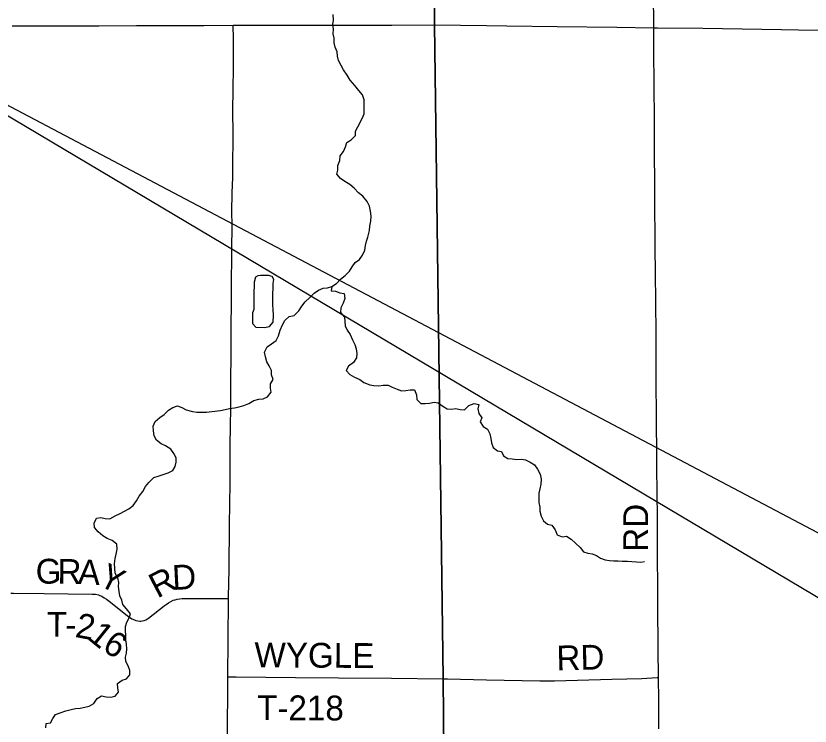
# Model space of a CAD drawing. Extents: x 0 to 34, y 0 to 22.
# Drawn here: x 26.924 to 28.741, y 13.678 to 15.303 of the extents above; entities that cross this region are included whole.
import ezdxf

# ---------------------------------------------------------------- set-up
doc = ezdxf.new("R2010")
doc.units = 0
for name, color, linetype in [('GM_X_Corporation', 7, 'Continuous'), ('GM_X_County_Road', 7, 'Continuous'), ('GM_X_County_Road_Text', 7, 'Continuous'), ('GM_X_Minor_Lake', 7, 'Continuous'), ('GM_X_Minor_River', 7, 'Continuous'), ('GM_X_State_Route', 7, 'Continuous'), ('GM_X_Township_Road', 7, 'Continuous'), ('GM_X_Township_Road_Text', 7, 'Continuous'), ('SH_Text', 7, 'Continuous')]:
    doc.layers.add(name, color=color, linetype=linetype)

msp = doc.modelspace()

# ---------------------------------------------------------------- linework, layer by layer
at = {"layer": 'GM_X_Corporation'}
for points in [[(26.7975, 12.7429), (27.3609, 12.7486), (27.363, 12.7493), (27.3691, 12.7502), (27.3721, 12.7505), (27.377, 12.7508), (27.3825, 12.7513), (27.879, 12.748), (27.9112, 12.7478), (27.9109, 12.7769), (27.9019, 13.7865), (27.8823, 15.2828), (27.8801, 15.6288), (27.88, 15.6409), (27.8849, 16.5038), (27.8821, 16.7067), (23.0715, 16.7067)], [(29.8715, 12.7899), (29.8715, 16.7067), (27.8821, 16.7067), (27.8849, 16.5038), (27.88, 15.6409), (27.8801, 15.6288), (27.8823, 15.2828), (27.9019, 13.7865), (27.9109, 12.7769)]]:
    msp.add_lwpolyline(points, dxfattribs=at)
at = {"layer": 'GM_X_County_Road'}
for points in [[(28.3839, 15.2757), (28.3837, 15.2989), (28.3832, 15.3343), (28.383, 15.3648), (28.3826, 15.3927), (28.3824, 15.4256), (28.3823, 15.4437), (28.3822, 15.4716), (28.3819, 15.4952), (28.3816, 15.522), (28.3814, 15.5425), (28.3812, 15.5598), (28.3809, 15.5896), (28.3807, 15.6017)], [(28.3948, 13.7889), (28.3944, 13.8084), (28.3939, 13.8336), (28.3936, 13.8749), (28.3932, 13.9339), (28.3927, 13.9799), (28.3927, 14.0178), (28.3926, 14.0433), (28.3926, 14.0713), (28.3924, 14.0887), (28.3923, 14.1266), (28.3923, 14.1519), (28.392, 14.1736), (28.3919, 14.1929), (28.3917, 14.2084), (28.3915, 14.2183), (28.3913, 14.227), (28.391, 14.2543), (28.3908, 14.2742), (28.3906, 14.2972), (28.3905, 14.3257), (28.3902, 14.3493), (28.3899, 14.3705), (28.3899, 14.3935), (28.3897, 14.4158), (28.3895, 14.4376), (28.3896, 14.4637), (28.3894, 14.4991), (28.3894, 14.5203), (28.3894, 14.5302), (28.389, 14.5687), (28.3889, 14.5942), (28.3888, 14.6296), (28.3883, 14.6688), (28.388, 14.6937), (28.3876, 14.7334), (28.3873, 14.7539), (28.3871, 14.7657), (28.387, 14.7869), (28.387, 14.8111), (28.3865, 14.8521), (28.3863, 14.8714), (28.3862, 14.8975), (28.386, 14.9366), (28.3857, 14.9727), (28.3856, 15.0006), (28.3856, 15.0404), (28.3854, 15.0647), (28.3853, 15.0914), (28.3848, 15.1175), (28.3845, 15.1535), (28.3844, 15.1715), (28.3841, 15.1964), (28.3838, 15.2318), (28.3839, 15.2573), (28.3839, 15.2757)], [(28.3957, 13.6713), (28.3952, 13.7432), (28.3949, 13.783), (28.3948, 13.7889)]]:
    msp.add_lwpolyline(points, dxfattribs=at)
at = {"layer": 'GM_X_Minor_Lake'}
msp.add_line((27.469, 14.6738), (27.4691, 14.6313), dxfattribs=at)
msp.add_lwpolyline([(27.4691, 14.6313), (27.4661, 14.6233), (27.4659, 14.6119), (27.4656, 14.5986), (27.4737, 14.5907), (27.4934, 14.5898), (27.5043, 14.5922), (27.5133, 14.6022), (27.5135, 14.6177), (27.513, 14.631), (27.5121, 14.6417), (27.512, 14.6553), (27.5122, 14.6667), (27.5128, 14.6796), (27.5131, 14.6903), (27.5149, 14.6998), (27.511, 14.7062), (27.5027, 14.7091), (27.4837, 14.7089), (27.4777, 14.7077), (27.4728, 14.705), (27.4699, 14.6936), (27.4696, 14.6818), (27.469, 14.6738)], dxfattribs=at)
at = {"layer": 'GM_X_Minor_River'}
for points in [[(27.7064, 15.0488), (27.7168, 15.0679), (27.7213, 15.0789), (27.7215, 15.0892), (27.721, 15.1006), (27.7213, 15.1105), (27.7177, 15.1222), (27.7093, 15.132), (27.6997, 15.1436), (27.6893, 15.1557), (27.682, 15.167), (27.6739, 15.1798), (27.6689, 15.1896), (27.6623, 15.2005), (27.6603, 15.2104), (27.6598, 15.2206), (27.6552, 15.2312), (27.6528, 15.2411), (27.6527, 15.2517), (27.6503, 15.2619), (27.6513, 15.2722), (27.6493, 15.2835), (27.6507, 15.2934), (27.6502, 15.3063)], [(27.2834, 14.2622), (27.289, 14.2718), (27.2911, 14.2817), (27.291, 14.2912), (27.2856, 14.3018), (27.2787, 14.3116), (27.2665, 14.319), (27.257, 14.3235), (27.2463, 14.3321), (27.2405, 14.3419), (27.2392, 14.3532), (27.2383, 14.3643), (27.2431, 14.3746), (27.2536, 14.3842), (27.2634, 14.3907), (27.2735, 14.4007), (27.2833, 14.4066), (27.2939, 14.4105), (27.3041, 14.4068), (27.314, 14.4012), (27.3281, 14.3972), (27.3383, 14.3958), (27.349, 14.3959), (27.3603, 14.3964), (27.3728, 14.3977), (27.3925, 14.4002), (27.403, 14.4023), (27.4132, 14.4043), (27.4242, 14.4056), (27.4356, 14.408), (27.4457, 14.4115), (27.4574, 14.4162), (27.4691, 14.4224), (27.48, 14.426), (27.4899, 14.4268), (27.4997, 14.4311), (27.5083, 14.4415), (27.507, 14.451), (27.5073, 14.4605), (27.5133, 14.4708), (27.509, 14.4817), (27.5089, 14.4912), (27.5042, 14.5018), (27.4984, 14.5116), (27.4956, 14.523), (27.4932, 14.5336), (27.4995, 14.5454), (27.5093, 14.5524), (27.5198, 14.5597), (27.5254, 14.5704), (27.5287, 14.5837), (27.5346, 14.5956), (27.5394, 14.6059), (27.5495, 14.6151), (27.5612, 14.6176), (27.5717, 14.6279), (27.5784, 14.6386), (27.5859, 14.6482), (27.5971, 14.6582), (27.6069, 14.6682), (27.6167, 14.6752), (27.6272, 14.6795), (27.6374, 14.6807), (27.6476, 14.6835), (27.6582, 14.6905), (27.6668, 14.7004), (27.678, 14.7089), (27.6878, 14.7185), (27.6937, 14.7289), (27.7004, 14.7384), (27.7102, 14.7454), (27.7177, 14.755), (27.7225, 14.7664), (27.7242, 14.7771), (27.7268, 14.7874), (27.7297, 14.7969), (27.7333, 14.8117), (27.734, 14.8216), (27.7361, 14.833), (27.7375, 14.8448), (27.7358, 14.8562), (27.7331, 14.8672), (27.728, 14.8781), (27.7184, 14.8902), (27.7085, 14.898), (27.6981, 14.9085), (27.6882, 14.9172), (27.6768, 14.9239), (27.6668, 14.9306), (27.6584, 14.9407), (27.6606, 14.9502), (27.6608, 14.9609), (27.6652, 14.9723), (27.6666, 14.9826), (27.6741, 14.9929), (27.6785, 15.0029), (27.6815, 15.0135), (27.6912, 15.0193), (27.7014, 15.029), (27.7016, 15.0388), (27.7064, 15.0488)], [(27.6476, 14.6835), (27.6458, 14.674), (27.6553, 14.673), (27.6652, 14.6693), (27.6754, 14.6679), (27.6767, 14.6561), (27.673, 14.6455), (27.6675, 14.6348), (27.6672, 14.6241), (27.676, 14.6136), (27.6773, 14.6034), (27.6774, 14.5939), (27.6824, 14.584), (27.689, 14.5739), (27.6948, 14.5614), (27.6998, 14.5512), (27.703, 14.541), (27.7042, 14.53), (27.7036, 14.5205), (27.6965, 14.5098), (27.6856, 14.5013), (27.6801, 14.4917), (27.6881, 14.482), (27.6992, 14.4764), (27.711, 14.4705), (27.7205, 14.4641), (27.7342, 14.4586), (27.7437, 14.4568), (27.7551, 14.4565), (27.7649, 14.4582), (27.7759, 14.4576), (27.7854, 14.4531), (27.7964, 14.4483), (27.8067, 14.4446), (27.8169, 14.4459), (27.8267, 14.4471), (27.8366, 14.4473), (27.8413, 14.4355), (27.8414, 14.4249), (27.851, 14.4159), (27.8608, 14.416), (27.871, 14.4165), (27.8812, 14.4189), (27.8907, 14.4171), (27.9014, 14.4097), (27.9109, 14.4037), (27.9208, 14.4027), (27.9306, 14.4043), (27.9409, 14.4022), (27.9507, 14.4011), (27.9605, 14.4111), (27.9725, 14.4162), (27.9839, 14.4133), (27.981, 14.4038), (27.9834, 14.3932), (27.9907, 14.3834), (27.9863, 14.3738), (27.9936, 14.3633), (28.0031, 14.3573), (28.0089, 14.3468), (28.0109, 14.3358), (28.0129, 14.3256), (28.0165, 14.3153), (28.026, 14.3079), (28.0355, 14.3061), (28.0402, 14.2959), (28.0497, 14.2899), (28.0599, 14.2889), (28.0705, 14.2875), (28.0808, 14.2888), (28.0906, 14.287), (28.1013, 14.2818), (28.1108, 14.2758), (28.1174, 14.2653), (28.1239, 14.2543), (28.126, 14.243), (28.1253, 14.2316), (28.1232, 14.2205), (28.121, 14.211), (28.1208, 14.1992), (28.1209, 14.1894), (28.1229, 14.1788), (28.123, 14.1693), (28.1258, 14.1579), (28.1312, 14.1477), (28.1407, 14.1399), (28.1502, 14.1373), (28.1583, 14.1264), (28.163, 14.1154), (28.1744, 14.111), (28.1842, 14.1119), (28.1945, 14.1056), (28.2049, 14.0966), (28.2156, 14.0864), (28.2229, 14.0763), (28.2331, 14.0737), (28.243, 14.072), (28.2525, 14.0683), (28.262, 14.0619), (28.2723, 14.0583), (28.2826, 14.0565)], [(26.993, 13.6737), (26.994, 13.6835), (27.0039, 13.6852), (27.0091, 13.6947), (27.0154, 13.7043), (27.026, 13.7082), (27.0384, 13.7122), (27.0509, 13.7154), (27.0611, 13.7177), (27.0713, 13.7186), (27.0822, 13.721), (27.0921, 13.7231), (27.1026, 13.7296), (27.1104, 13.7407), (27.1202, 13.7465), (27.1312, 13.7448), (27.1411, 13.7438), (27.1513, 13.7458), (27.1595, 13.7554), (27.1579, 13.7652), (27.1566, 13.7751), (27.1675, 13.7828), (27.1777, 13.7856), (27.1848, 13.7951), (27.1851, 13.805), (27.1812, 13.8152), (27.1761, 13.8258), (27.1749, 13.8353), (27.1774, 13.8448), (27.1785, 13.8547), (27.1772, 13.8653), (27.176, 13.8752), (27.1759, 13.8854), (27.1754, 13.8953), (27.1753, 13.9055), (27.1782, 13.9154), (27.1834, 13.925), (27.1863, 13.9349), (27.1775, 13.9462), (27.1694, 13.956), (27.1666, 13.9658), (27.1624, 13.976), (27.1607, 13.9859), (27.1595, 13.9969), (27.1597, 14.0064), (27.1574, 14.017), (27.1519, 14.0279), (27.151, 14.0389), (27.1498, 14.0492), (27.1516, 14.061), (27.1541, 14.0712), (27.1559, 14.0823), (27.1557, 14.0937), (27.1447, 14.1026), (27.1336, 14.1067), (27.123, 14.1134), (27.113, 14.122), (27.1042, 14.1318), (27.1033, 14.1417), (27.1085, 14.1531), (27.1187, 14.1547), (27.1286, 14.1526), (27.1392, 14.1519), (27.1516, 14.1589), (27.1629, 14.164), (27.1727, 14.1698), (27.1829, 14.1745), (27.1926, 14.1822), (27.2001, 14.1933), (27.2068, 14.2036), (27.2146, 14.2144), (27.2213, 14.2258), (27.2288, 14.2354), (27.24, 14.2466), (27.2502, 14.2497), (27.2615, 14.2536), (27.2729, 14.2572), (27.2834, 14.2622)], [(28.2826, 14.0565), (28.2924, 14.0558), (28.3023, 14.0556), (28.3117, 14.0549), (28.3235, 14.0547), (28.3337, 14.0544), (28.344, 14.0534), (28.3538, 14.0528), (28.3625, 14.054)]]:
    msp.add_lwpolyline(points, dxfattribs=at)
at = {"layer": 'GM_X_State_Route'}
msp.add_lwpolyline([(26.9161, 15.2801), (26.9255, 15.2801), (27.0074, 15.2801), (27.1143, 15.2802), (27.2007, 15.2806), (27.3001, 15.2811), (27.3541, 15.2813), (27.4214, 15.2815), (27.5697, 15.2819), (27.7842, 15.2819), (27.8807, 15.2822), (27.8825, 15.2822), (28.0011, 15.2809), (28.0477, 15.2802), (28.1627, 15.2787), (28.2994, 15.2769), (28.3839, 15.2757), (28.392, 15.2756), (28.4964, 15.2747), (28.6759, 15.2718), (28.715, 15.271), (28.8462, 15.2696)], dxfattribs=at)
at = {"layer": 'GM_X_Township_Road'}
for points in [[(27.411, 13.9693), (27.4111, 13.9735), (27.412, 14.0362), (27.4133, 14.1405), (27.4139, 14.1833), (27.4144, 14.2368), (27.4146, 14.2736), (27.4147, 14.3008), (27.4148, 14.3083), (27.4156, 14.376), (27.416, 14.3927), (27.4164, 14.4137), (27.4165, 14.4486), (27.4165, 14.4778), (27.4166, 14.5182), (27.4167, 14.5418), (27.417, 14.5977), (27.4176, 14.6406), (27.4176, 14.6487), (27.4179, 14.6592), (27.418, 14.6771), (27.4187, 14.7683), (27.4191, 14.8228), (27.4187, 14.8561), (27.4187, 14.8692), (27.4192, 14.8838), (27.4196, 14.8976), (27.4205, 14.9327), (27.4213, 15.0517), (27.4211, 15.0667), (27.4211, 15.0809), (27.4218, 15.14), (27.4219, 15.1797), (27.422, 15.2152), (27.422, 15.2506), (27.4214, 15.2815)], [(26.9126, 13.9819), (26.9186, 13.9818), (26.989, 13.981), (27.0989, 13.9799), (27.1062, 13.9792), (27.1134, 13.9777), (27.1168, 13.9765), (27.1207, 13.9748), (27.1265, 13.9714), (27.1316, 13.9679), (27.1376, 13.9636), (27.1407, 13.961)], [(27.1407, 13.961), (27.1757, 13.9327), (27.1817, 13.9281), (27.1864, 13.925), (27.1897, 13.9232), (27.1955, 13.9206), (27.1991, 13.9194), (27.2034, 13.9183), (27.2079, 13.9179), (27.2104, 13.918), (27.2142, 13.9184), (27.2179, 13.9195), (27.2215, 13.9209), (27.2254, 13.923), (27.2281, 13.9247), (27.2639, 13.9525), (27.2684, 13.9558), (27.2734, 13.9594), (27.2791, 13.963), (27.2846, 13.9656), (27.2886, 13.9669), (27.2934, 13.9681), (27.2994, 13.9691), (27.305, 13.9695), (27.3173, 13.9699), (27.4049, 13.9693), (27.411, 13.9693)], [(27.4096, 13.7903), (27.4104, 13.876), (27.4103, 13.8945), (27.4107, 13.9486), (27.411, 13.9693)], [(27.4084, 13.6505), (27.4086, 13.6897), (27.4085, 13.7068), (27.409, 13.7288), (27.4091, 13.7474), (27.4093, 13.7626), (27.4096, 13.7903)], [(27.4096, 13.7903), (27.4285, 13.7901), (27.5644, 13.7891), (27.6625, 13.7883), (27.7835, 13.7874), (27.9021, 13.7859)], [(27.9021, 13.7859), (27.9122, 13.7858), (28.0009, 13.7838), (28.1232, 13.7812), (28.1569, 13.7814), (28.2875, 13.7852), (28.3565, 13.7869), (28.3919, 13.7887), (28.3948, 13.7889)]]:
    msp.add_lwpolyline(points, dxfattribs=at)
at = {"layer": 'SH_Text'}
msp.add_lwpolyline([(30.3847, 13.262), (26.5546, 15.2831), (30.3847, 13.0053)], close=True, dxfattribs=at)

# ---------------------------------------------------------------- texts
at = {"layer": 'GM_X_County_Road_Text'}
msp.add_text('RD', height=0.05682, rotation=90, dxfattribs=at).set_placement((28.3709, 14.0766))
at = {"layer": 'GM_X_Township_Road_Text'}
for s, height, rotation, p in [('G', 0.0568, 359.2678, (26.9693, 14.004)), ('R', 0.0568, 359.2506, (27.0193, 14.0034)), ('A', 0.0568, 357.0517, (27.0654, 14.0028)), ('Y', 0.0568, 333.448, (27.1094, 14.0018)), ('D', 0.0568, 2.9155, (27.2833, 13.989)), ('R', 0.0568, 27.56, (27.2481, 13.9691)), ('T', 0.0568, 359.5414, (26.9949, 13.8822)), ('2', 0.0568, 349.1422, (27.0581, 13.8819)), ('-', 0.0568, 359.5439, (27.0374, 13.8819)), ('1', 0.0568, 321.1866, (27.0858, 13.8784)), ('6', 0.0568, 328.3183, (27.1194, 13.852)), ('WYGLE', 0.05682, 359.6183, (27.4701, 13.8123)), ('RD', 0.05682, 1.4826, (28.1618, 13.8048)), ('T-218', 0.05682, 359.7193, (27.4761, 13.6914))]:
    msp.add_text(s, height=height, rotation=rotation, dxfattribs=at).set_placement(p)

doc.saveas('drawing.dxf')
